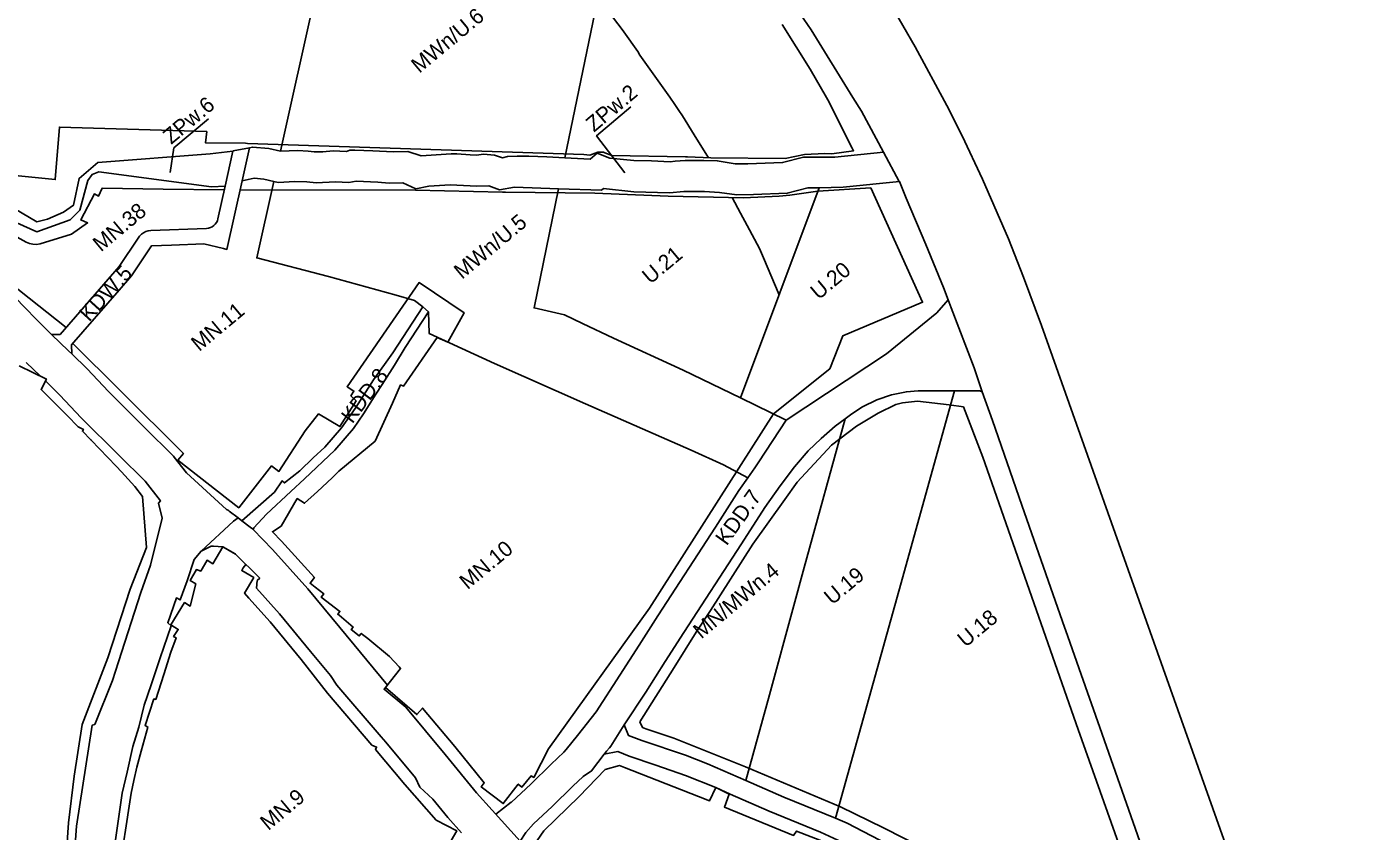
# Model space of a CAD drawing. Extents: x 7418616 to 7420822, y 5550745 to 5553106.
# Drawn here: x 7420139.9 to 7420570.2, y 5552194.8 to 5552455 of the extents above; entities that cross this region are included whole.
import ezdxf

# ---------------------------------------------------------------- set-up
doc = ezdxf.new("R2010")
doc.units = 0
for name, color, linetype in [('granica obszaru objętego planem', 7, 'Continuous'), ('granica strefy zwiększonej wysokości zabudowy', 7, 'Continuous'), ('linie rozgraniczające', 7, 'Continuous'), ('nieprzekraczalne linie zabudowy', 7, 'Continuous'), ('przeznaczenia terenów', 7, 'Continuous')]:
    doc.layers.add(name, color=color, linetype=linetype)

msp = doc.modelspace()

# ---------------------------------------------------------------- linework, layer by layer
at = {"layer": 'granica obszaru objętego planem'}
msp.add_lwpolyline([(7420419.04, 5552462.29), (7420427.01, 5552448.46), (7420437.26, 5552429.47), (7420442.19, 5552419.71), (7420448.72, 5552405.7), (7420457.17, 5552386.45), (7420461.96, 5552374), (7420467.81, 5552358.36), (7420579.74, 5552042.73), (7420611.64, 5551954.27), (7420788.95, 5551466.82)], dxfattribs=at)
at = {"layer": 'granica strefy zwiększonej wysokości zabudowy'}
for points in [[(7420360.16, 5552412.61), (7420360.16, 5552412.61), (7420355.62, 5552420.03), (7420351.85, 5552426.17), (7420350.65, 5552427.9), (7420349.31, 5552429.84), (7420347.68, 5552432.18), (7420338.03, 5552445.82), (7420337.35, 5552446.91), (7420332.86, 5552453.3), (7420332.61, 5552453.66), (7420324.64, 5552464.17), (7420324.44, 5552464.43)], [(7420383.03, 5552368.29), (7420378.02, 5552380.21), (7420376.71, 5552383.32), (7420372.74, 5552390.7), (7420372.71, 5552390.74), (7420370.6, 5552394.66), (7420367.83, 5552399.75), (7420367.83, 5552399.76)]]:
    msp.add_lwpolyline(points, dxfattribs=at)
at = {"layer": 'linie rozgraniczające'}
for p, q in [((7420221.91, 5552414.74), (7420233.88, 5552468.44)), ((7420206.48, 5552414.76), (7420203.99, 5552403.43)), ((7420209.49, 5552405.19), (7420211.84, 5552415.86)), ((7420395.96, 5552402.87), (7420370.6, 5552335.03)), ((7420269.75, 5552362.75), (7420267.89, 5552364.41)), ((7420370.6, 5552335.03), (7420385.33, 5552327.78)), ((7420205.34, 5552298.37), (7420208.25, 5552296.16)), ((7420208.25, 5552296.16), (7420209.42, 5552295.27)), ((7420290.31, 5552201.68), (7420299.38, 5552191.7))]:
    msp.add_line(p, q, dxfattribs=at)
for points in [[(7420416.74, 5552414.43), (7420409.61, 5552427.64), (7420406.88, 5552432.07), (7420393.44, 5552454), (7420388.62, 5552460.88), (7420382.31, 5552461.66), (7420377.62, 5552462.24), (7420379.66, 5552473.65), (7420372.66, 5552483.63), (7420365.27, 5552493.34), (7420352.62, 5552509.96), (7420344.77, 5552517.74), (7420339.58, 5552522.86), (7420328.42, 5552533.88), (7420326.21, 5552536.05), (7420315.68, 5552545.3)], [(7420300.78, 5552467.8), (7420301.43, 5552467.7), (7420314.7, 5552466.83), (7420324.73, 5552465.85), (7420313.8, 5552412.59)], [(7420419.04, 5552462.29), (7420427.01, 5552448.46), (7420437.26, 5552429.47), (7420442.19, 5552419.71), (7420448.72, 5552405.7), (7420457.17, 5552386.45), (7420461.96, 5552374), (7420467.81, 5552358.36), (7420579.74, 5552042.73), (7420611.64, 5551954.27), (7420788.95, 5551466.82)], [(7420206.48, 5552414.76), (7420199.14, 5552413.85), (7420162.83, 5552411.03), (7420156.8, 5552405.92), (7420155, 5552397.26), (7420151.77, 5552395.04), (7420146.63, 5552392.74), (7420143.18, 5552391.94), (7420128.29, 5552400.63), (7420118.98, 5552404.25)], [(7420211.84, 5552415.86), (7420206.57, 5552414.8), (7420206.48, 5552414.76)], [(7420211.84, 5552415.86), (7420212.84, 5552416.06), (7420218.11, 5552415.58), (7420221.91, 5552414.74)], [(7420313.8, 5552412.59), (7420307.99, 5552412.91), (7420302.15, 5552413.07), (7420298.39, 5552413.08), (7420295.24, 5552413.01), (7420293.61, 5552412.62), (7420291.01, 5552413.48), (7420287.49, 5552413.76), (7420285.23, 5552413.46), (7420283.21, 5552413.55), (7420278.92, 5552413.83), (7420277.08, 5552413.91), (7420267.35, 5552413.26), (7420263.03, 5552414.59), (7420258.29, 5552414.48), (7420251.75, 5552414.81), (7420245.88, 5552415.07), (7420244.35, 5552415.05), (7420243.21, 5552414.62), (7420238.9, 5552414.86), (7420235.56, 5552414.52), (7420232.73, 5552414.56), (7420230.87, 5552414.79), (7420227.49, 5552414.94), (7420221.95, 5552414.73), (7420221.91, 5552414.74)], [(7420313.8, 5552412.59), (7420321.93, 5552412.13), (7420324.19, 5552414.08), (7420328.31, 5552412.5), (7420336.09, 5552411.69), (7420341.8, 5552411.57), (7420347.86, 5552411.29), (7420349.42, 5552411.49), (7420352.67, 5552411.71), (7420355.62, 5552411.77), (7420358.7, 5552411.67), (7420363.06, 5552411.64), (7420368.85, 5552410.66), (7420372.92, 5552410.68), (7420384.17, 5552411.04), (7420390.93, 5552412.84), (7420401, 5552412.85), (7420416.74, 5552414.43)], [(7420416.74, 5552414.43), (7420421.86, 5552404.96), (7420421.89, 5552404.89)], [(7420203.99, 5552403.43), (7420199.57, 5552403.26), (7420163.24, 5552408.03), (7420161, 5552407.23), (7420159.6, 5552405.3), (7420157.09, 5552395.64), (7420153.95, 5552392.56), (7420143.19, 5552388.69), (7420136.72, 5552391.55), (7420128.56, 5552397.25), (7420121.84, 5552401.24), (7420119.69, 5552400.93)], [(7420154.46, 5552349.18), (7420154.34, 5552352.08), (7420169.78, 5552369.85), (7420173.79, 5552374.45), (7420180.2, 5552384.12), (7420186.69, 5552384.36), (7420197.12, 5552384.74), (7420203.46, 5552383.26), (7420204.61, 5552383), (7420209.49, 5552405.19)], [(7420219.73, 5552404.97), (7420216.56, 5552405.68), (7420213.37, 5552405.97), (7420209.49, 5552405.19)], [(7420267.89, 5552364.41), (7420265.18, 5552366.46), (7420259.31, 5552368.15), (7420237.44, 5552374.2), (7420214.21, 5552380.21), (7420219.73, 5552404.97)], [(7420219.73, 5552404.97), (7420221.13, 5552404.66), (7420226.55, 5552404.97), (7420230.39, 5552404.81), (7420233.4, 5552404.49), (7420239.71, 5552404.8), (7420243.98, 5552404.56), (7420246.37, 5552405.08), (7420253.33, 5552404.68), (7420257.01, 5552404.44), (7420261.39, 5552404.55), (7420265.62, 5552402.6), (7420269.89, 5552403.4), (7420276.71, 5552403.89), (7420285.33, 5552403.39), (7420289.22, 5552403.58), (7420292.72, 5552402.29), (7420297.55, 5552403.11), (7420311.75, 5552402.61)], [(7420421.89, 5552404.89), (7420403.78, 5552403.09), (7420395.96, 5552402.87)], [(7420437.65, 5552366.72), (7420436.16, 5552370.61), (7420430.42, 5552384.54), (7420424.12, 5552399.56), (7420421.89, 5552404.89)], [(7420147.87, 5552355.44), (7420143.56, 5552359.75), (7420138.73, 5552364.79), (7420134.72, 5552368.9), (7420132.01, 5552371.82), (7420129.55, 5552375.01), (7420127.33, 5552377.61), (7420125.99, 5552380.21), (7420124.9, 5552382.74), (7420123.7, 5552386.34), (7420122.54, 5552389.63), (7420121.39, 5552393.15), (7420119.69, 5552400.93)], [(7420203.99, 5552403.43), (7420201.67, 5552392.89), (7420201.49, 5552392.26), (7420201.21, 5552391.68), (7420200.84, 5552391.15), (7420200.38, 5552390.69), (7420199.85, 5552390.31), (7420199.27, 5552390.03), (7420198.65, 5552389.85), (7420198, 5552389.78), (7420180.02, 5552389.12), (7420179.19, 5552389), (7420178.39, 5552388.75), (7420177.64, 5552388.37), (7420176.95, 5552387.88), (7420176.35, 5552387.29), (7420175.86, 5552386.61), (7420169.81, 5552377.49), (7420164.84, 5552371.79), (7420150.7, 5552355.51), (7420147.87, 5552355.44)], [(7420311.75, 5552402.61), (7420303.83, 5552364.04), (7420313.66, 5552361.8), (7420319.49, 5552359.06), (7420329.51, 5552354.31), (7420352.03, 5552343.91), (7420370.6, 5552335.03)], [(7420395.96, 5552402.87), (7420392.35, 5552402.83), (7420385.64, 5552401.14), (7420374.75, 5552400.74), (7420369.38, 5552400.58), (7420363.8, 5552401.39), (7420358.91, 5552401.66), (7420352.21, 5552401.68), (7420347.57, 5552401.29), (7420336.05, 5552401.64), (7420326.24, 5552402.66), (7420325.63, 5552402.13), (7420311.75, 5552402.61)], [(7420437.65, 5552366.72), (7420434.02, 5552362.51), (7420417.74, 5552349.24), (7420385.33, 5552327.78)], [(7420448.7, 5552336.96), (7420446.02, 5552344.7), (7420438.62, 5552364.13), (7420437.65, 5552366.72)], [(7420267.89, 5552364.41), (7420258.18, 5552349.58), (7420251.92, 5552340.82), (7420246.02, 5552331.5), (7420241.58, 5552325.32), (7420236.22, 5552319.02), (7420232.41, 5552315.61), (7420228.18, 5552311.35), (7420223.24, 5552307.48), (7420222.43, 5552308.16), (7420219.97, 5552304.53), (7420209.42, 5552295.27)], [(7420213.04, 5552292.39), (7420213.29, 5552292.95), (7420217.35, 5552297.39), (7420225.21, 5552304.73), (7420229.66, 5552308.8), (7420239.41, 5552318.1), (7420245.46, 5552325.03), (7420248.73, 5552329.79), (7420252.7, 5552336.21), (7420254.78, 5552339.33), (7420258.77, 5552345.58), (7420262.2, 5552351.23), (7420269.75, 5552362.75)], [(7420372.97, 5552309.16), (7420365.06, 5552313.29), (7420354.63, 5552318.13), (7420320.46, 5552333.03), (7420291.04, 5552346.1), (7420269.92, 5552355.82), (7420269.75, 5552362.75)], [(7420154.46, 5552349.18), (7420153.43, 5552350.19), (7420147.87, 5552355.44)], [(7420205.34, 5552298.37), (7420204.97, 5552298.64), (7420204.48, 5552298.93), (7420191.5, 5552310.76), (7420187.49, 5552315.86), (7420187.28, 5552316.12), (7420187.01, 5552316.41), (7420178.31, 5552325.11), (7420166.32, 5552336.99), (7420159.4, 5552344.33), (7420154.46, 5552349.18)], [(7420139.67, 5552346.39), (7420144.36, 5552341.98), (7420146.26, 5552341.05), (7420145.94, 5552340.45), (7420150.61, 5552335.87), (7420157.51, 5552328.55), (7420169.71, 5552316.45), (7420178.12, 5552308.04), (7420183.08, 5552301.68), (7420182.53, 5552300.97), (7420183.68, 5552296.06), (7420179.9, 5552280.93), (7420176.75, 5552272.02), (7420169.51, 5552249.63), (7420167.66, 5552243.65), (7420161.89, 5552229.36), (7420161.05, 5552229.2), (7420156.02, 5552196.51), (7420153.71, 5552165)], [(7420401.2, 5552199.16), (7420421.67, 5552272.47), (7420439.74, 5552337.24)], [(7420439.74, 5552337.24), (7420437.04, 5552337.21), (7420427.93, 5552337.21), (7420424.16, 5552336.96), (7420419.37, 5552335.95), (7420414.64, 5552334.35), (7420410.03, 5552332.05), (7420406.5, 5552329.81), (7420404.38, 5552328.23)], [(7420439.74, 5552337.24), (7420447.89, 5552337.3), (7420448.7, 5552336.96)], [(7420448.7, 5552336.96), (7420451.94, 5552327.62), (7420461.42, 5552300.34), (7420463.82, 5552293.51), (7420474.63, 5552262.64), (7420476.31, 5552257.86), (7420480.62, 5552245.56), (7420486.65, 5552228.38), (7420501.73, 5552185.39), (7420507.3, 5552169.51), (7420511.47, 5552157.62), (7420510.58, 5552150.44)], [(7420333.01, 5552229.24), (7420339.96, 5552239.88), (7420346.25, 5552249.71), (7420352.24, 5552259.12), (7420370.89, 5552287.76), (7420378.38, 5552299.51), (7420383.42, 5552306.6), (7420387.95, 5552312.7), (7420392.42, 5552317.89), (7420396.64, 5552321.84), (7420401.19, 5552325.85), (7420404.38, 5552328.23)], [(7420404.38, 5552328.23), (7420391.18, 5552280.16), (7420387.81, 5552267.9), (7420379.88, 5552238.99), (7420372.27, 5552211.26)], [(7420385.33, 5552327.78), (7420376.48, 5552314.35), (7420375.23, 5552312.35), (7420372.97, 5552309.16)], [(7420291.49, 5552200.38), (7420296.45, 5552204.29), (7420296.58, 5552204.3), (7420302.76, 5552210.09), (7420309.38, 5552216.62), (7420313.44, 5552220.49), (7420314.17, 5552221.26), (7420317.85, 5552225.87), (7420323.87, 5552233.54), (7420331.55, 5552245.3), (7420337.82, 5552255.08), (7420343.84, 5552264.55), (7420362.5, 5552293.2), (7420370.01, 5552304.99), (7420372.97, 5552309.16)], [(7420196.22, 5552285.43), (7420206.68, 5552295.14), (7420208.25, 5552296.16)], [(7420209.42, 5552295.27), (7420212.14, 5552293.22), (7420212.81, 5552292.63), (7420213.04, 5552292.39)], [(7420213.04, 5552292.39), (7420219.31, 5552285.92), (7420230.77, 5552273.29), (7420241.04, 5552260.73), (7420256.43, 5552242.16), (7420255.39, 5552240.79), (7420262.38, 5552234.99), (7420275.13, 5552219.68), (7420285.21, 5552207.29), (7420290.31, 5552201.68)], [(7420165.63, 5552162.35), (7420165.79, 5552163.56), (7420166.88, 5552173.32), (7420167.39, 5552182.4), (7420168.63, 5552192.12), (7420170.71, 5552207.15), (7420172.35, 5552214.02), (7420174.2, 5552222.27), (7420176.1, 5552228.5), (7420177.86, 5552235.65), (7420180.13, 5552242.24), (7420182.98, 5552250.89), (7420186.53, 5552261.31), (7420185.48, 5552262.3), (7420188.25, 5552270.3), (7420189.45, 5552269.64), (7420191.78, 5552275.82), (7420194.01, 5552282.71), (7420196.22, 5552285.43)], [(7420196.22, 5552285.43), (7420199.55, 5552287.03), (7420200.16, 5552286.99), (7420200.22, 5552286.94), (7420200.25, 5552286.99), (7420203.3, 5552286.79), (7420207.25, 5552284.61), (7420215.17, 5552276.75), (7420214.4, 5552275.92), (7420214.17, 5552273.43), (7420221.62, 5552265.21), (7420231.62, 5552252.98), (7420238.08, 5552245.19), (7420240.15, 5552242.14), (7420254.47, 5552225.38), (7420255.89, 5552223.73), (7420265.53, 5552212.15), (7420266.93, 5552209.16), (7420271.11, 5552205.29), (7420275.99, 5552199.28), (7420280.43, 5552194.41)], [(7420333.01, 5552229.24), (7420328.62, 5552222.44), (7420328.17, 5552221.85), (7420327.22, 5552220.77), (7420327.06, 5552220.47), (7420326.54, 5552219.79)], [(7420372.27, 5552211.26), (7420359.89, 5552216.66), (7420352.78, 5552219.49), (7420338.64, 5552224.23), (7420334.31, 5552225.83), (7420333.01, 5552229.24)], [(7420299.38, 5552191.7), (7420301.18, 5552194.46), (7420303.69, 5552197.26), (7420309.64, 5552202.83), (7420316.37, 5552209.46), (7420319.68, 5552212.62), (7420322.42, 5552214.39), (7420326.54, 5552219.79)], [(7420326.54, 5552219.79), (7420330.88, 5552220.61), (7420334.57, 5552219.2), (7420343.23, 5552216.21), (7420352.73, 5552212.89), (7420362.54, 5552209.07), (7420367.26, 5552206.9), (7420379.81, 5552201.42), (7420396.44, 5552194.54), (7420402.05, 5552191.99), (7420416.32, 5552184.66), (7420426.58, 5552179.37), (7420437.35, 5552174.15), (7420448.25, 5552168.67), (7420453.73, 5552166.18), (7420470.56, 5552159.75), (7420488.72, 5552152.48), (7420490.75, 5552151.65)], [(7420401.2, 5552199.16), (7420384.57, 5552205.89), (7420372.27, 5552211.26)], [(7420510.58, 5552150.44), (7420486.58, 5552159.81), (7420470.3, 5552166.54), (7420453.57, 5552173.11), (7420431.71, 5552183.65), (7420418.04, 5552190.76), (7420405.05, 5552197.48), (7420401.2, 5552199.16)]]:
    msp.add_lwpolyline(points, dxfattribs=at)
at = {"layer": 'nieprzekraczalne linie zabudowy'}
for points in [[(7420384, 5552455.73), (7420393.09, 5552441.22), (7420398.38, 5552432.08), (7420398.78, 5552431.35), (7420406.65, 5552415.73), (7420407.1, 5552414.87), (7420400.08, 5552413.89), (7420397.78, 5552413.96), (7420391.25, 5552413.64), (7420385.03, 5552412.39), (7420360.99, 5552412.57), (7420353.46, 5552412.91), (7420352.8, 5552412.91), (7420328.94, 5552413.37), (7420326.76, 5552414.18), (7420326.24, 5552414.41), (7420324.48, 5552414.43), (7420321.86, 5552413.47), (7420319.91, 5552413.69), (7420211.19, 5552417.26), (7420210.61, 5552417.29), (7420197.68, 5552417.42), (7420198.08, 5552421.05), (7420150.46, 5552422.54), (7420149.1, 5552405.54), (7420121.07, 5552408.4)], [(7420152.62, 5552357.72), (7420137.53, 5552369.65), (7420128.64, 5552377.15), (7420136.8, 5552386.98), (7420139.71, 5552385.37), (7420140.75, 5552384.9), (7420141.9, 5552384.64), (7420143.07, 5552384.6), (7420144.23, 5552384.79), (7420154.31, 5552387.89), (7420159.58, 5552391.56), (7420157.36, 5552392.49), (7420161.78, 5552400.91), (7420163.11, 5552400.23), (7420164.23, 5552402.73), (7420183.98, 5552402.44), (7420203.73, 5552402.24)], [(7420154.77, 5552352.57), (7420170.06, 5552337.4), (7420190.52, 5552316.97), (7420188.74, 5552314.82), (7420208.41, 5552299.44), (7420219.01, 5552312.98), (7420221.4, 5552311.21), (7420229.86, 5552324.38), (7420234.23, 5552329.79), (7420241.08, 5552325.68), (7420246.35, 5552334.06), (7420244.66, 5552335.61), (7420245.65, 5552337.16), (7420243.4, 5552338.6), (7420266.69, 5552372.24), (7420281.28, 5552362.44), (7420275.99, 5552353.03), (7420272.53, 5552354.48), (7420261.66, 5552338.82), (7420260.73, 5552339.19), (7420258.07, 5552333.3), (7420252.48, 5552321.03), (7420240.71, 5552311.26), (7420238.63, 5552309.17), (7420233.83, 5552304.76), (7420229.68, 5552300.9), (7420227.3, 5552302.42), (7420222.15, 5552293.52), (7420219.27, 5552291.71), (7420222.23, 5552288.66), (7420232.87, 5552276.92), (7420231.44, 5552275.04), (7420233.09, 5552273.81), (7420235.89, 5552271.67), (7420235.02, 5552270.57), (7420241.09, 5552265.93), (7420240.39, 5552265.05), (7420240.81, 5552264.72), (7420245.38, 5552260.91), (7420244.73, 5552260.11), (7420247.34, 5552258.02), (7420248.02, 5552258.84), (7420250.1, 5552257.23), (7420257.15, 5552251.35), (7420260.26, 5552248.06), (7420260.69, 5552247.54), (7420255.81, 5552241.4), (7420265.97, 5552232.59), (7420267.81, 5552234.72), (7420278.21, 5552222.25), (7420287.75, 5552210.49), (7420286.78, 5552209.19), (7420293.86, 5552203.8), (7420298.72, 5552210.13), (7420299.92, 5552209.14), (7420302.88, 5552212.77), (7420303.74, 5552212.29), (7420308.46, 5552221.49), (7420341.14, 5552267), (7420381.2, 5552329.81), (7420399.42, 5552344.41), (7420403.65, 5552355.04), (7420429.4, 5552365.89), (7420412.67, 5552402.89), (7420395.58, 5552401.84), (7420386.47, 5552400.48), (7420383.09, 5552400.16), (7420371.5, 5552399.68), (7420347.15, 5552400.19), (7420323.45, 5552401.14), (7420294.64, 5552401.52), (7420293.66, 5552401.44), (7420265.54, 5552402.14), (7420208.84, 5552402.23)], [(7420152.15, 5552178.72), (7420153.39, 5552197.55), (7420155.24, 5552212.71), (7420157.8, 5552229.38), (7420166.1, 5552250.92), (7420173.37, 5552273.19), (7420178.64, 5552286.63), (7420177.34, 5552303.15), (7420174.88, 5552306.28), (7420170.51, 5552311.08), (7420168.82, 5552312.91), (7420160.71, 5552321.28), (7420160.73, 5552321.32), (7420160.63, 5552321.37), (7420157.91, 5552324.18), (7420158.19, 5552324.76), (7420156.51, 5552325.63), (7420152.99, 5552329.27), (7420144.53, 5552337.69), (7420146.26, 5552341.05), (7420137.49, 5552345.36)], [(7420503.34, 5552160.95), (7420479.66, 5552227.74), (7420448.85, 5552315.86), (7420442.57, 5552332.08), (7420437.98, 5552332.77), (7420427.8, 5552333.97), (7420422.89, 5552333.37), (7420420.79, 5552332.87), (7420415.09, 5552330.08), (7420408.01, 5552325.82), (7420399.91, 5552319.71), (7420388.89, 5552307.74), (7420384.85, 5552302.16), (7420374.52, 5552287.71), (7420360.83, 5552266.22), (7420356.21, 5552259.25), (7420349.15, 5552247.77), (7420337.98, 5552230.21)], [(7420171.05, 5552190.34), (7420171.98, 5552196.61), (7420172.98, 5552202.95), (7420173.69, 5552207.22), (7420174.55, 5552211.29), (7420175.5, 5552215.6), (7420176.85, 5552220.78), (7420179.04, 5552228.58), (7420178.13, 5552229.04), (7420180.97, 5552237.64), (7420181.61, 5552237.49), (7420184.18, 5552245.6), (7420186.5, 5552252.75), (7420188.16, 5552257.42), (7420187.34, 5552257.89), (7420188.85, 5552260.14), (7420186.45, 5552261.65), (7420190.9, 5552268.8), (7420192.74, 5552267.67), (7420194.51, 5552274.82), (7420192.67, 5552275.97), (7420194.75, 5552279.46), (7420196.13, 5552279), (7420198.2, 5552282.49), (7420200.08, 5552281.37), (7420203.3, 5552286.79), (7420207.39, 5552284.47), (7420210.74, 5552281.14), (7420209.88, 5552280.02), (7420209.39, 5552279.13), (7420213.24, 5552276.89), (7420210.31, 5552271.83), (7420211.63, 5552270.27), (7420218.59, 5552262.6), (7420228.53, 5552250.44), (7420237.11, 5552239.54), (7420251.46, 5552222.74), (7420252.95, 5552222.08), (7420252.65, 5552221.36), (7420262.13, 5552209.98), (7420272.23, 5552198.5), (7420278.84, 5552195), (7420275.54, 5552189.35)], [(7420337.98, 5552230.21), (7420338.86, 5552228.43), (7420339.99, 5552228), (7420349.01, 5552224.97), (7420372.17, 5552215.67), (7420402.84, 5552202.81), (7420416.71, 5552195.95), (7420443.24, 5552182.54)], [(7420304.81, 5552191.91), (7420307.02, 5552195.01), (7420318.43, 5552206.13), (7420326.78, 5552214.87), (7420331.4, 5552216.13), (7420333.12, 5552215.47), (7420356.94, 5552206.14), (7420360.51, 5552204.68), (7420362.54, 5552209.07), (7420366.93, 5552206.82), (7420365.33, 5552202.71), (7420387.71, 5552193.54), (7420388.63, 5552194.94), (7420398.14, 5552191.25)]]:
    msp.add_lwpolyline(points, dxfattribs=at)
at = {"layer": 'przeznaczenia terenów'}
for points in [[(7420186.21, 5552407.84), (7420187.4, 5552415.78), (7420198.59, 5552425.21)], [(7420333.14, 5552407.76), (7420324.02, 5552419.74), (7420335.14, 5552429.1)]]:
    msp.add_lwpolyline(points, dxfattribs=at)

# ---------------------------------------------------------------- texts
for s, rotation, p in [('MWn/U.6', 39.8439, (7420266.76, 5552439.73)), ('ZPw.2', 40.1, (7420323.22, 5552420.7)), ('ZPw.6', 40.1, (7420186.59, 5552416.74)), ('MN.38', 39.8439, (7420163.87, 5552381.99)), ('MWn/U.5', 39.8439, (7420280.56, 5552373.13)), ('U.21', 39.8439, (7420341.4, 5552371.54)), ('KDW.5', 47.5867, (7420160.08, 5552359.34)), ('U.20', 39.8439, (7420395.79, 5552366.47)), ('MN.11', 39.8439, (7420195.63, 5552349.78)), ('KDD.8', 53.0257, (7420245.11, 5552326.4)), ('KDD.7', 54.3594, (7420366.1, 5552286.95)), ('MN.10', 39.8439, (7420282.36, 5552272.79)), ('MN/MWn.4', 39.8439, (7420357.88, 5552256.86)), ('U.19', 39.8439, (7420400.18, 5552267.83)), ('U.18', 39.8439, (7420443.27, 5552254.11)), ('MN.9', 39.8439, (7420217.96, 5552194.92))]:
    msp.add_text(s, height=5, rotation=rotation, dxfattribs=at).set_placement(p)

doc.saveas('drawing.dxf')
